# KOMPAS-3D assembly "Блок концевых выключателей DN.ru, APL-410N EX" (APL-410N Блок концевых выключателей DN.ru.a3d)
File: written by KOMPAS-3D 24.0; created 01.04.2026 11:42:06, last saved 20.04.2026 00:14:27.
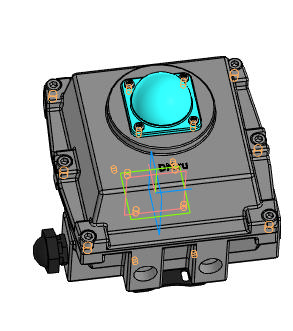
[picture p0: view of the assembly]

Document properties: Автор: R2D2; Полное имя файла: E:\Работа\Зайцев\Аксессуары для пневмоприводов\Блок концевых выключателей DN.ru\APL-410N EX Блок концевых выключателей DN.ru\исходные материалы\APL-410N Блок концевых выключателей DN.ru.a3d

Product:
- Component [detail]: Деталь  | qty 1  | pos. 1  | Автор: R2D2; source file: 1.m3d
- Component [detail]: Деталь  | qty 1  | pos. 2  | Автор: R2D2; source file: 2.m3d
- Component [detail]: Деталь  | qty 1  | pos. 4  | Масса: 0.159642; source file: Деталь.m3d
- Component [detail]: Деталь  | qty 2  | pos. 5  | Масса: 0.047126; Автор: R2D2; source file: Деталь1.m3d
- Component [standard]: Cheese head screw ISO 7048 - М5 x 10 - H  | qty 4  | Материал: Не определено (density 0 kg/m3); Масса: 0.00255; Раздел спецификации: Стандартные изделия; Рассекать на разрезах: no
- Component [standard]: Hexagon socket head cap screw ISO 4762 - М6 x 10  | qty 4  | Материал: Не определено (density 0 kg/m3); Масса: 0.0047; Раздел спецификации: Стандартные изделия; Рассекать на разрезах: no
- Component [standard]: Hexagon socket head cap screw ISO 4762 - М5 x 8  | qty 4  | Материал: Не определено (density 0 kg/m3); Масса: 0.00245; Раздел спецификации: Стандартные изделия; Рассекать на разрезах: no
- Component [detail]: Деталь  | qty 1  | pos. 6  | Масса: 0.399627; Автор: R2D2; source file: 3.m3d
- Component [standard]: Hexagon socket head cap screw ISO 4762 - М8 x 12  | qty 6  | Материал: Не определено (density 0 kg/m3); Масса: 0.0109; Раздел спецификации: Стандартные изделия; Рассекать на разрезах: no
- Component [detail]: Деталь  | qty 1  | pos. 7  | Масса: 0.143875; Автор: R2D2; source file: Деталь2.m3d
- Body: Тело 1  | qty 1
    Масса: 10.198824
- Part/product: Блок концевых выключателей DN.ru  | designation APL-410N EX
    Масса: 1.1
    Раздел спецификации: Прочие изделия
    Примечание: D290-00324

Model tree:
1. Массив по концентрической сетке:1  (4 pattern instances)
     Шаг 2 = 360
2. Эскиз:1  (with: Грань.Элемент выдавливания:17, Ребро.Скругление:21)
3. Элемент выдавливания:1
     Расстояние 2 = 8
4. Зеркальный массив:1
5. Экземпляр ( 1 )
6. Экземпляр ( 2 )  (with: Элемент выдавливания:1)
7. Эскиз:2  (with: Грань.Элемент выдавливания:18)  (labels: Ребро.Элемент выдавливания:19.Экземпляр ( 2 ))
8. Элемент выдавливания:2
     Расстояние 1 = 2
9. Эскиз:3  (with: Грань.Элемент выдавливания:3)
10. Элемент выдавливания:3  (with: Грань.Элемент выдавливания:9, Грань.Листовое тело:1, Грань.Элемент выдавливания:2, Грань.Элемент выдавливания:8, Грань.Элемент выдавливания:1, Грань.Элемент выдавливания:16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)  (labels: Грань.Тело 1.Экземпляр ( 1, 3 ); Грань.Элемент выдавливания:1.Экземпляр ( 2 ))
     Расстояние 1 = 0.5; Ориентация = 2; Ориентация = 2; Ориентация = 2

Referenced files in E:\Работа\Зайцев\Аксессуары для пневмоприводов\Блок концевых выключателей DN.ru\APL-410N EX Блок концевых выключателей DN.ru\исходные материалы\: 1.m3d, 2.m3d, Деталь.m3d, Деталь1.m3d, 3.m3d, Деталь2.m3d
Referenced files in C:\Program Files\ASCON\KOMPAS-3D v24\Libs\PolynomLib\DATA\vault\Methods\Kompas\3D\: PLib_Screw_ISO_7048_1500.m3d, PLib_Screw_DIN_7984_1500.m3d
Referenced files in E:\Работа\Зайцев\Аксессуары для пневмоприводов\Блок концевых выключателей DN.ru\APL-310N Блок концевых выключателей DN.ru\исходные материалы\: Деталь1.m3d
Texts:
  Cheese head screw
  BOSimple***PART:5fbac98a-f0ab-87b8-89d4-94a9c7ed4dc2***SHORTLOC:B94B_D4FD7824BC314902[H;0,8;10;5;-;Undefined]
  Hexagon socket head cap screw
  BOSimple***PART:86906dfe-320b-4a65-fedb-73bd2ba9e651***SHORTLOC:A259_235BDFABBEFC4171[1;10;6;-;Undefined]
  BOSimple***PART:2d8c9a95-15dc-3e7c-f94e-4ac000f9c72a***SHORTLOC:A259_235BDFABBEFC4171[0,8;8;5;-;Undefined]
  BOSimple***PART:b7fb87e8-e11b-0771-c746-2cb1e6324b0d***SHORTLOC:A259_235BDFABBEFC4171[1,25;12;8;-;Undefined]
  Программные изделия  и базы данных
  APL-410N EX
  Деталь (1)
  Cheese head screw ISO 7048 - М5 x 10 - H (1)
  Hexagon socket head cap screw ISO 4762 - М6 x 10 (1)
  Hexagon socket head cap screw ISO 4762 - М5 x 8 (1)
  Hexagon socket head cap screw ISO 4762 - М5 x 8 (2)
  Hexagon socket head cap screw ISO 4762 - М5 x 8 (3)
  Деталь (2)
  Hexagon socket head cap screw ISO 4762 - М5 x 8 (4)
  Hexagon socket head cap screw ISO 4762 - М6 x 10 (2)
  Cheese head screw ISO 7048 - М5 x 10 - H (2)
  Hexagon socket head cap screw ISO 4762 - М6 x 10 (3)
  Cheese head screw ISO 7048 - М5 x 10 - H (3)
  Hexagon socket head cap screw ISO 4762 - М6 x 10 (4)
  Cheese head screw ISO 7048 - М5 x 10 - H (4)
  Hexagon socket head cap screw ISO 4762 - М8 x 12 (1)
  Hexagon socket head cap screw ISO 4762 - М8 x 12 (2)
  Hexagon socket head cap screw ISO 4762 - М8 x 12 (3)
  Hexagon socket head cap screw ISO 4762 - М8 x 12 (4)
  Hexagon socket head cap screw ISO 4762 - М8 x 12 (5)
  Hexagon socket head cap screw ISO 4762 - М8 x 12 (6)
  Ось Y.Начало координат
  Плоскость ZY.Начало координат
  Плоскость XY.Начало координат
  Грань.Pan flat head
